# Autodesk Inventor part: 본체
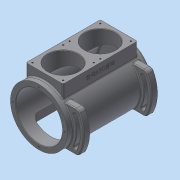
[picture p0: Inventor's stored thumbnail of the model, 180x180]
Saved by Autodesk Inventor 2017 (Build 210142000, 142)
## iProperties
Created: 2016-11
Part Number: 본체
Material: 알루미늄 6061
Document SubType Name: Modeling
Designer: mduedu
Density: 2.71 g/cm^3
Appearance: 기본값
Author: mduedu
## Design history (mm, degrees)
sketch "스케치1"
  geometry: C1 r 65 at (0, 0); 1 further point
  constraints: 1 centre point, 1 coincident
  dimensions: "d119" = 130 diameter of C1
extrude "돌출1" new body sketch "스케치1" distance "d3" = 98; taper "d4" = 0 deg; dims "d132" = 97, "d133" = 0
feature "쉘1" dims "d120" = 12, "d134" = 8
node "작업 평면2"
sketch "스케치13"
  geometry: L1 (42.5, 85)-(-42.5, 85); L2 (-42.5, 85)-(-42.5, -85); L3 (-42.5, -85)-(42.5, -85); L4 (42.5, -85)-(42.5, 85); 2 further points
  constraints: 8 end point, 2 parallel, 1 horizontal, 1 midpoint, 1 perpendicular, 1 vertical alignment
  dimensions: "d122" = 170 distance of L1.end L2.end; "d124" = 85 distance of L2.end L3.end; "d125" = 85 distance from line of point (0, 0) L1 (= 0.5 x d122)
extrude "돌출11" join sketch "스케치13" stored distance "d126" = 10; taper "d127" = 0 deg
sketch "스케치14"
  geometry: L1 (65, 97)-(-65, 97) reference; C1 r 35 at (0, 42.5); 1 further point
  constraints: 1 centre point, 1 vertical alignment
  dimensions: "d128" = 70 diameter of C1; "d129" = 54.5 distance from line of C1.centre L1
extrude "돌출12" cut sketch "스케치14" stored distance "d130" = 10; taper "d131" = 0 deg
sketch "스케치15"
  geometry: C1 r 53 at (0, 0) reference; 1 further point
extrude "돌출13" cut sketch "스케치15" stored distance "d135" = 10; taper "d136" = 0 deg
chamfer "모따기1" distance "d54" = 1; stored, may be unused: second distance "d55" = 2, angle "d56" = 45 deg
sketch "스케치8"
  geometry: C1 r 30 at (0, 0); C2 r 65 at (0, 0) reference; 1 further point
  constraints: 1 centre point, 1 concentric
  dimensions: "d57" = 60 diameter of C1
extrude "돌출8" join sketch "스케치8" distance "d58" = 14; taper "d59" = 0 deg
hole "구멍3" diameter "d62" = 41; stored, may be unused: countersink angle "d66" = 90 deg, drill point angle "d68" = 0 deg; dims "d63" = 6, "d64" = 47, "d65" = 14, "d67" = 17, "d195" = 10, "d196" = 10
fillet "모깎기11" dims "d69" = 3
fillet "모깎기12" dims "d70" = 3
fillet "모깎기13" dims "d71" = 0.3
chamfer "모따기2" distance "d72" = 1; stored, may be unused: second distance "d73" = 2, angle "d74" = 45 deg
node "작업 평면3"
sketch "스케치16"
  geometry: L1 (-42.5, -80)-(47.5, -80); L2 (-42.5, -80)-(21.14, -16.36); L3 (-42.5, -80)-(21.14, -143.64); L4 (3.462, -34.038)-(34.879, -34.038); L5 (3.462, -125.962)-(34.879, -125.962); A1 r 65 centre (-42.5, -80) between (3.462, -34.038) and (3.462, -125.962) reference; A2 r 90 centre (-42.5, -80) between (34.879, -125.962) and (34.879, -34.038); A3 r 90 centre (-42.5, -80) between (34.879, -34.038) and (34.879, -125.962); A4 r 65 centre (-42.5, -80) between (3.462, -125.962) and (3.462, -34.038); 1 further point
  constraints: 11 point on circle, 10 end point, 3 centre point, 2 parallel, 2 point on line, 1 coincident, 1 horizontal
  dimensions: "d140" = 45 deg angle of L3 L1; "d141" = 45 deg angle of L2 L1; "d142" = 25 radial gap between concentric circles of A1 A2
extrude "돌출14" join sketch "스케치16" distance "d143" = 15; taper "d144" = 0 deg
sketch "스케치17"
  geometry: L1 (-42.5, -80)-(34.414, -80); L2 (-42.5, -80)-(27.208, -47.495); L3 (-42.5, -80)-(27.208, -112.505); L4 (34.879, -34.038)-(3.462, -34.038) reference; L5 (3.462, -125.962)-(34.879, -125.962) reference; A1 r 65 centre (-42.5, -80) between (3.462, -34.038) and (3.462, -125.962) reference; A2 r 76.914 centre (-42.5, -80) between (19.17, -125.962) and (19.17, -34.038); A3 r 4 centre (27.208, -47.495) between (23.582, -49.185) and (30.833, -45.804); A4 r 4 centre (27.208, -112.505) between (30.833, -114.196) and (23.582, -110.815); A5 r 80.914 centre (-42.5, -80) between (30.833, -114.196) and (30.833, -45.804); A6 r 72.914 centre (-42.5, -80) between (23.582, -110.815) and (23.582, -49.185); 1 further point
  constraints: 13 point on circle, 6 end point, 5 centre point, 5 coincident, 3 midpoint, 2 point on line, 1 equal radius, 1 horizontal
  dimensions: "d145" = 25 deg angle of L1 L3; "d146" = 25 deg angle of L2 L1; "d147" = 8 diameter of A3
extrude "돌출15" cut sketch "스케치17" stored distance "d150" = 15; taper "d151" = 0 deg
fillet "모깎기17" dims "d152" = 10
fillet "모깎기18" dims "d153" = 2
fillet "모깎기19" dims "d154" = 2
chamfer "모따기4" distance "d155" = 1; stored, may be unused: second distance "d156" = 2, angle "d157" = 45 deg
fillet "모깎기20" dims "d159" = 3
fillet "모깎기21" dims "d160" = 3
fillet "모깎기22" dims "d161" = 3
node "작업 평면4"
sketch "스케치18"
  geometry: L1 (-42.5, 70)-(42.5, 70); L2 (42.5, 70)-(42.5, -70); L3 (42.5, -70)-(-42.5, -70); L4 (-42.5, -70)-(-42.5, 70); 2 further points
  constraints: 8 end point, 2 parallel, 1 horizontal, 1 midpoint, 1 perpendicular, 1 vertical alignment
  dimensions: "d162" = 140 distance of L1.end L2.end; "d164" = 85 distance of L2.end L3.end; "d165" = 70 distance from line of point (0, 0) L1 (= 0.5 x d162)
extrude "돌출16" cut sketch "스케치18" stored distance "d166" = 15; taper "d167" = 0 deg
fillet "모깎기23" dims "d168" = 10
fillet "모깎기24" dims "d173" = 3
sketch "스케치19"
  geometry: 4 further points
  constraints: 4 other
hole "구멍6" sketch "스케치19" at (0, -59), (59, 0), (-59, 0), (0, 59) diameter "d174" = 3.242; stored, may be unused: countersink angle "d178" = 90 deg, drill point angle "d180" = 120 deg; dims "d175" = 8, "d176" = 4, "d177" = 2, "d179" = 10
sketch "스케치20"
  geometry: L1 (35, -77.5)-(-35, -77.5); L2 (-35, -77.5)-(-35, -7.5); L3 (-35, -7.5)-(35, -7.5); L4 (35, -7.5)-(35, -77.5); L5 (35, -77.5)-(-35, -7.5); L6 (-35, -77.5)-(35, -7.5); C1 r 36 at (0, -42.5) reference; 5 further points
  constraints: 12 end point, 4 coincident, 2 midpoint, 2 parallel, 1 horizontal, 1 perpendicular
  dimensions: "d181" = 70 distance of L2.end L3.end; "d182" = 70 distance of L1.end L2.end
hole "구멍7" sketch "스케치20" at (-35, -77.5), (-35, -7.5), (35, -7.5), (35, -77.5) diameter "d183" = 3.242; stored, may be unused: countersink angle "d187" = 90 deg, drill point angle "d189" = 118 deg; dims "d184" = 8, "d185" = 4, "d186" = 2, "d188" = 10
sketch "스케치21"
  geometry: L1 (164, 0)-(0, 0) reference; L2 (-3, 0)-(-3, -24.649) reference; 3 further points
  constraints: 1 midpoint, 1 vertical alignment, 1 other
  dimensions: "d190" = 15 distance from line of point (82, -15) L1; "d191" = 85 distance from line of point (82, 0) L2 (derived)
feature "엠보싱2" sketch "스케치21" dims "d3" = 98, "d4" = 0, "d119" = 130, "d132" = 97, "d133" = 0, "d192" = 0.5, "d193" = 0
node "솔리드1"
mirror "대칭5"
mirror "대칭6"
mirror "대칭7"
